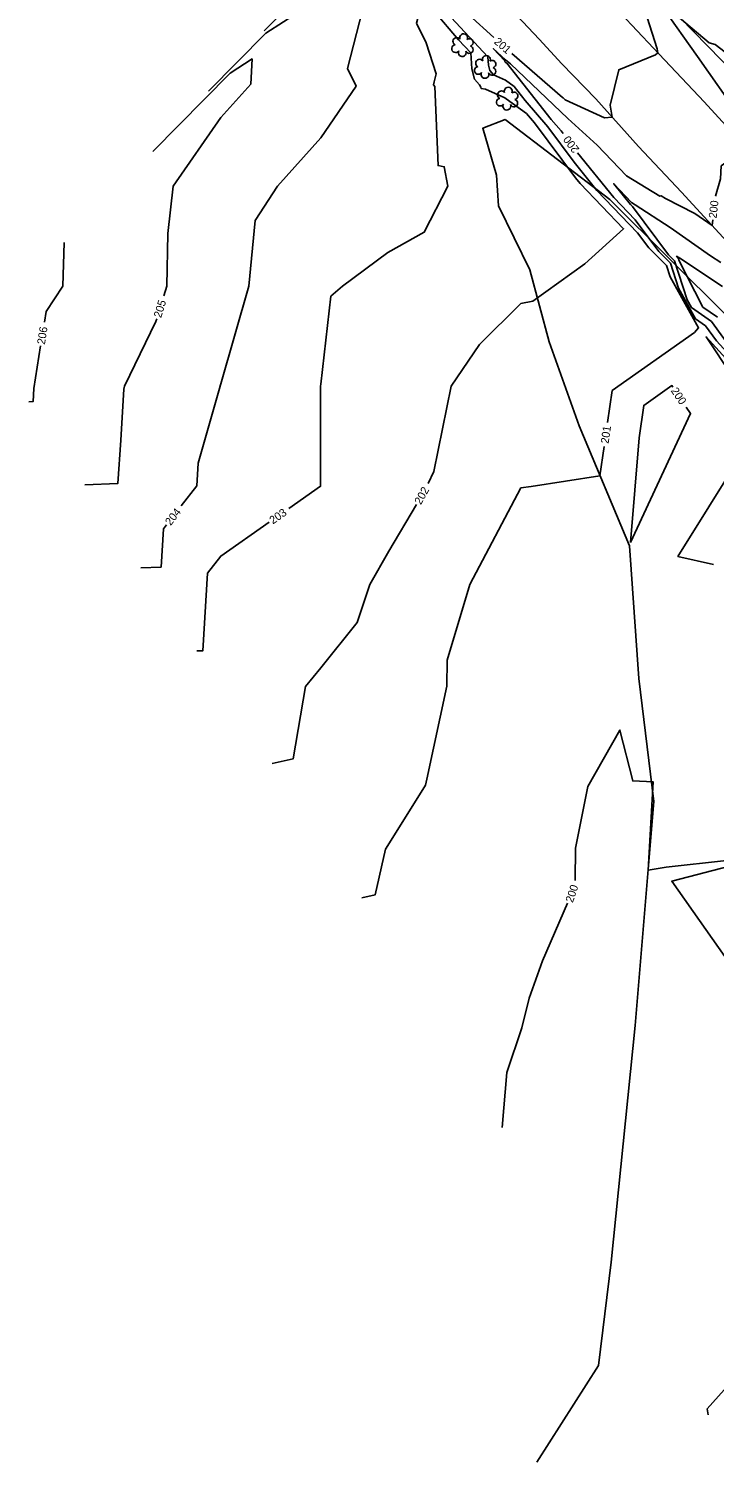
# Model space of a CAD drawing. Extents: x 2086416 to 2115205, y 575507 to 632762.
# Drawn here: x 2109949.5 to 2110120.8, y 581916.1 to 582274.4 of the extents above; entities that cross this region are included whole.
import ezdxf

# ---------------------------------------------------------------- set-up
doc = ezdxf.new("R2010")
doc.units = 0
for name, color, linetype in [('DTM Contours Major', 7, 'Continuous'), ('DTM Contours Major Text', 7, 'Continuous'), ('DTM Contours Minor', 7, 'Continuous'), ('DTM Contours Minor Text', 7, 'Continuous'), ('Exist Hydrographic FEMA Cross Section', 7, 'Continuous'), ('Exist Roads EOP', 7, 'Continuous'), ('Exist Vegetation Shrub CELL', 7, 'Continuous'), ('Exist Vegetation Woods Line', 7, 'Continuous')]:
    doc.layers.add(name, color=color, linetype=linetype)

# ---------------------------------------------------------------- blocks, each defined once
blk = doc.blocks.new('EXIST VEGETATION SHRUB')
at = {"layer": 'Exist Vegetation Shrub CELL'}
blk.add_line((0, 0), (0, 0), dxfattribs=at)
for centre, radius, start, end in [((-0.036, -0.0141), 0.0191, 95.10992, 327.95341), ((-0.0297, 0.0225), 0.0194, 35.89076, 245.42165), ((0.0046, 0.0408), 0.0198, 334.83907, 200.47174), ((0.0334, 0.0174), 0.0186, 284.45672, 126.08612), ((-0.0026, -0.0337), 0.0197, 151.27966, 21.38702), ((0.0327, -0.0186), 0.0187, 204.99133, 73.46012)]:
    blk.add_arc(centre, radius, start, end, dxfattribs=at)

msp = doc.modelspace()

# ---------------------------------------------------------------- linework, layer by layer
at = {"layer": 'DTM Contours Major'}
for points in [[(2110139.1, 582259.08), (2110135.66, 582260.25), (2110126, 582266.59), (2110120.98, 582270.39), (2110119.48, 582270.82), (2110107.88, 582280.62), (2110107.79, 582280.67), (2110107.65, 582280.8), (2110106.39, 582281.73), (2110107.13, 582280.82), (2110107.89, 582279.73), (2110116.56, 582267.38), (2110127.02, 582252.6), (2110128.41, 582250.45), (2110129.6, 582248.74), (2110128.93, 582245.49), (2110128.68, 582244.73), (2110127.92, 582243.98), (2110122.51, 582240.09), (2110122.35, 582236.81), (2110121.07, 582232.55)], [(2110120.4, 582226.6), (2110120.27, 582225.14), (2110115.94, 582228.14), (2110108.58, 582231.97), (2110107.48, 582232.63), (2110107.15, 582232.52), (2110098.82, 582237.61), (2110091.52, 582245.28), (2110084.17, 582251.94), (2110069.86, 582265.54), (2110068.65, 582266.59), (2110065.58, 582269.39), (2110068.47, 582266.29), (2110068.49, 582266.13), (2110068.51, 582266.04), (2110068.58, 582265.96), (2110068.8, 582265.85), (2110068.96, 582265.74), (2110080.07, 582251.64), (2110082.51, 582248.8), (2110083.01, 582248.14)], [(2109980.52, 582243.69), (2109999.86, 582263.28), (2110005.33, 582266.8), (2110004.98, 582260.49), (2109997.53, 582252.16), (2109985.6, 582235.01), (2109984.29, 582223.22), (2109983.99, 582210.01), (2109983.26, 582207.61)], [(2110086.65, 582243.38), (2110095.68, 582232.16), (2110101, 582226.63), (2110106.9, 582218.72), (2110109.82, 582215.75), (2110111.89, 582209.48), (2110116.13, 582201.87), (2110118.59, 582200.15), (2110121.31, 582196.4), (2110137.22, 582178.92), (2110139.86, 582175.47), (2110149.85, 582167.21)], [(2109981.52, 582201.87), (2109981.31, 582201.2), (2109973.45, 582185.01), (2109973.24, 582184.27), (2109972.5, 582171.5), (2109971.78, 582160.71), (2109963.51, 582160.39)], [(2110099.85, 582145.93), (2110102.02, 582172.15), (2110103.18, 582180.21), (2110110.21, 582185.17), (2110110.46, 582184.79)], [(2110113.79, 582179.8), (2110114.86, 582178.19), (2110099.85, 582145.93)], [(2110123.82, 582066.52), (2110108.81, 582064.84), (2110104.3, 582064.09), (2110105.52, 582086.17), (2110100.43, 582086.39), (2110097.21, 582099.07), (2110089.24, 582085.01), (2110086.09, 582069.62), (2110086.03, 582061.46)], [(2110154.11, 582021.23), (2110142.55, 582015.25), (2110110.16, 582061.32), (2110134.87, 582067.76), (2110129.78, 582067.19)], [(2110084.13, 582055.85), (2110077.85, 582041.39), (2110074.58, 582032.08), (2110072.69, 582024.7), (2110068.99, 582013.49), (2110067.79, 581999.76)]]:
    msp.add_lwpolyline(points, dxfattribs=at)
at = {"layer": 'DTM Contours Minor'}
for points in [[(2110008.36, 582273.85), (2110017.6, 582283.2), (2110035.78, 582294.88), (2110045.01, 582284.9), (2110047.45, 582279.81), (2110046.42, 582275.74), (2110048.77, 582270.85), (2110051.34, 582263.12), (2110050.77, 582261.05), (2110050.67, 582260.36), (2110050.96, 582259.93), (2110051.79, 582240.17), (2110053.34, 582239.88), (2110054.19, 582234.99), (2110048.32, 582223.48), (2110039.2, 582218.43), (2110027.88, 582210.01), (2110025, 582207.52), (2110022.5, 582185.57), (2110022.45, 582185.01), (2110022.43, 582184.94), (2110022.43, 582160.01), (2110014.52, 582154.48)], [(2109994.44, 582258.77), (2110008.73, 582273.24), (2110035.26, 582290.28), (2110035.13, 582287.82), (2110029.17, 582264.4), (2110031.29, 582260), (2110022.5, 582247.11), (2110011.69, 582235.01), (2110006.08, 582226.42), (2110004.5, 582210.01), (2109997.5, 582185.58), (2109997.37, 582185.15), (2109997.31, 582185.02), (2109991.84, 582165.81), (2109991.51, 582160.14), (2109987.61, 582155.09)], [(2110050.82, 582278.78), (2110056.91, 582271.61), (2110059.95, 582268.35), (2110060.26, 582264.36), (2110060.92, 582261.78), (2110062.13, 582260.3), (2110062.5, 582259.74), (2110062.52, 582259.45), (2110063.63, 582259.24), (2110068.48, 582257.06), (2110068.77, 582256.86), (2110073.89, 582253.15), (2110075.85, 582250.87), (2110086.14, 582237.08), (2110087.3, 582235.65), (2110098.15, 582224.38), (2110088.48, 582215.57), (2110075.43, 582206.3), (2110072.5, 582205.71), (2110062.12, 582195.46), (2110055.02, 582185.03), (2110050.74, 582163.73), (2110049.27, 582160.68)], [(2110055.08, 582277.12), (2110064.21, 582267.32), (2110064.38, 582265.25), (2110064.72, 582263.91), (2110065.6, 582262.82), (2110068.64, 582261.46), (2110070.76, 582259.93), (2110073.56, 582256.38), (2110079.18, 582249.83), (2110085.75, 582241.03), (2110091.49, 582233.9), (2110101.65, 582223.35), (2110104.47, 582219.58), (2110108.83, 582215.15), (2110109.74, 582212.36), (2110116.87, 582199.58), (2110115.81, 582198.41), (2110095.28, 582183.92), (2110094.13, 582175.93)], [(2110065.71, 582272.12), (2110059.45, 582277.85)], [(2110104.03, 582277.19), (2110106.53, 582269.37), (2110106.7, 582268.34), (2110106.11, 582267.85), (2110096.94, 582264.09), (2110094.75, 582255.22), (2110095.28, 582252.26), (2110093.4, 582252.06), (2110083.51, 582256.62), (2110083.01, 582257.07), (2110082.89, 582257.19), (2110070.23, 582268.17)], [(2110122.45, 582215.91), (2110119.87, 582217.62), (2110109.78, 582224.7), (2110101.02, 582230.38), (2110100.15, 582230.92), (2110095.68, 582235.61), (2110099.86, 582230.42), (2110100.35, 582229.91), (2110109.33, 582217.86), (2110110.82, 582216.35), (2110114.03, 582206.61), (2110115.1, 582204.68), (2110120.09, 582201.2), (2110125.58, 582193.61)], [(2109958.38, 582220.9), (2109958.01, 582210.01), (2109953.85, 582203.66), (2109953.44, 582201.02)], [(2110122.81, 582209.92), (2110112.15, 582217), (2110111.78, 582217.26), (2110111.39, 582217.51), (2110111.76, 582217.01), (2110111.82, 582216.95), (2110112.01, 582216.36), (2110117.94, 582204.78), (2110121.58, 582202.24)], [(2110198, 582099.45), (2110197.53, 582100), (2110183.27, 582121.94), (2110180.25, 582125.54), (2110167.91, 582142), (2110166.4, 582143.94), (2110155.77, 582159.69), (2110152.29, 582164.48), (2110137.14, 582177), (2110136.59, 582177.72), (2110118.74, 582197.32), (2110131.92, 582177.57), (2110127.14, 582167.29), (2110111.7, 582142.48), (2110120.58, 582140.49)], [(2109952.5, 582195.09), (2109950.83, 582184.45), (2109950.62, 582181.19), (2109949.51, 582181.14)], [(2110093.28, 582169.99), (2110092.22, 582162.65), (2110075.04, 582159.94), (2110072.5, 582159.61), (2110059.69, 582135.46), (2110054.02, 582116.6), (2110053.99, 582110.1), (2110049.01, 582086.79), (2110048.61, 582085.35), (2110047.57, 582083.56), (2110038.65, 582069.29), (2110036.05, 582057.91), (2110032.72, 582057.18)], [(2110046.36, 582155.43), (2110039.47, 582143.79), (2110034.75, 582135.43), (2110031.58, 582125.99), (2110022.5, 582114.63), (2110018.66, 582110.01), (2110015.59, 582091.92), (2110010.33, 582090.76)], [(2109983.94, 582150.34), (2109983.16, 582149.34), (2109982.59, 582139.83), (2109977.51, 582139.63)], [(2110009.61, 582151.04), (2109997.5, 582142.56), (2109994.21, 582138.3), (2109993.04, 582118.93), (2109991.52, 582118.87)], [(2110208.9, 582036.78), (2110159.35, 582011.14), (2110149.92, 581962.12), (2110128.92, 581940.56), (2110118.98, 581929.46), (2110119.3, 581928.01)]]:
    msp.add_lwpolyline(points, dxfattribs=at)
at = {"layer": 'Exist Hydrographic FEMA Cross Section'}
msp.add_lwpolyline([(2110126.05, 582262.96), (2110119.11, 582270.07), (2110112.17, 582277.18)], dxfattribs=at)
at = {"layer": 'Exist Roads EOP'}
for points in [[(2110283.42, 582080.08), (2110269.79, 582094.77), (2110258.57, 582106.89), (2110244.84, 582121.04), (2110232.61, 582133.97), (2110220.43, 582147.01), (2110205.56, 582162.74), (2110193.7, 582175.26), (2110182.38, 582187.32), (2110170.57, 582200.14), (2110157.55, 582213.9), (2110148.13, 582223.91), (2110139.67, 582233.18), (2110129.17, 582244.2), (2110118.25, 582256.11), (2110105.57, 582269.53), (2110093.37, 582282.59), (2110082.14, 582294.76), (2110071.88, 582305.53), (2110059.32, 582319.17)], [(2110044.03, 582306.54), (2110057.72, 582292.25), (2110067.42, 582282.08), (2110077.05, 582271.73), (2110082.67, 582265.54), (2110091.18, 582256.81), (2110101.9, 582244.92), (2110112.61, 582233.51), (2110124.83, 582220.15), (2110138.66, 582205.71), (2110150.44, 582192.87), (2110163.31, 582179.2), (2110176.51, 582165.18), (2110187.09, 582154.1), (2110200.16, 582140.29), (2110212.15, 582128.06), (2110221.2, 582117.92), (2110235.62, 582102.6), (2110247.94, 582089.65), (2110262.41, 582074.68), (2110272.71, 582063.48), (2110283.25, 582052.48)]]:
    msp.add_lwpolyline(points, dxfattribs=at)
at = {"layer": 'Exist Vegetation Woods Line'}
for points in [[(2110076.47, 581916.11), (2110091.85, 581940.31), (2110095.05, 581966.16), (2110101.03, 582025.24), (2110105.7, 582081.27), (2110101.91, 582111.98), (2110099.6, 582145.14), (2110087.04, 582175.13), (2110079.58, 582196.1), (2110074.74, 582214.13), (2110066.9, 582230.06), (2110066.42, 582237.72), (2110062.96, 582249.48), (2110068.55, 582251.65)], [(2110068.55, 582251.65), (2110094.73, 582231.68), (2110124.29, 582202.28), (2110166.88, 582155.97), (2110198.23, 582122.47), (2110225.6, 582089.15), (2110269.57, 582041.09)]]:
    msp.add_lwpolyline(points, dxfattribs=at)

# ---------------------------------------------------------------- block references
at = {"layer": 'Exist Vegetation Shrub CELL', "xscale": 50, "yscale": 50}
for p in [(2110057.95, 582270.06), (2110063.63, 582264.63), (2110069.09, 582256.71)]:
    msp.add_blockref('EXIST VEGETATION SHRUB', p, dxfattribs=at)

# ---------------------------------------------------------------- texts
at = {"layer": 'DTM Contours Major Text'}
for s, rotation, p in [('200', 127.4642, (2110087.18, 582244.27)), ('200', 83.5266, (2110121.36, 582226.89)), ('205', 73.0822, (2109982.59, 582201.96)), ('200', 303.7059, (2110109.85, 582183.91)), ('200', 71.315, (2110085.44, 582055.81))]:
    msp.add_text(s, height=2, rotation=rotation, dxfattribs=at).set_placement(p)
at = {"layer": 'DTM Contours Minor Text'}
for s, rotation, p in [('201', 318.7867, (2110065.59, 582270.87)), ('206', 81.0751, (2109953.55, 582195.33)), ('201', 81.8171, (2110094.37, 582170.57)), ('202', 60.9732, (2110047.48, 582155.26)), ('204', 52.2869, (2109984.97, 582150.04)), ('203', 34.9948, (2110010.51, 582150.44))]:
    msp.add_text(s, height=2, rotation=rotation, dxfattribs=at).set_placement(p)

doc.saveas('drawing.dxf')
